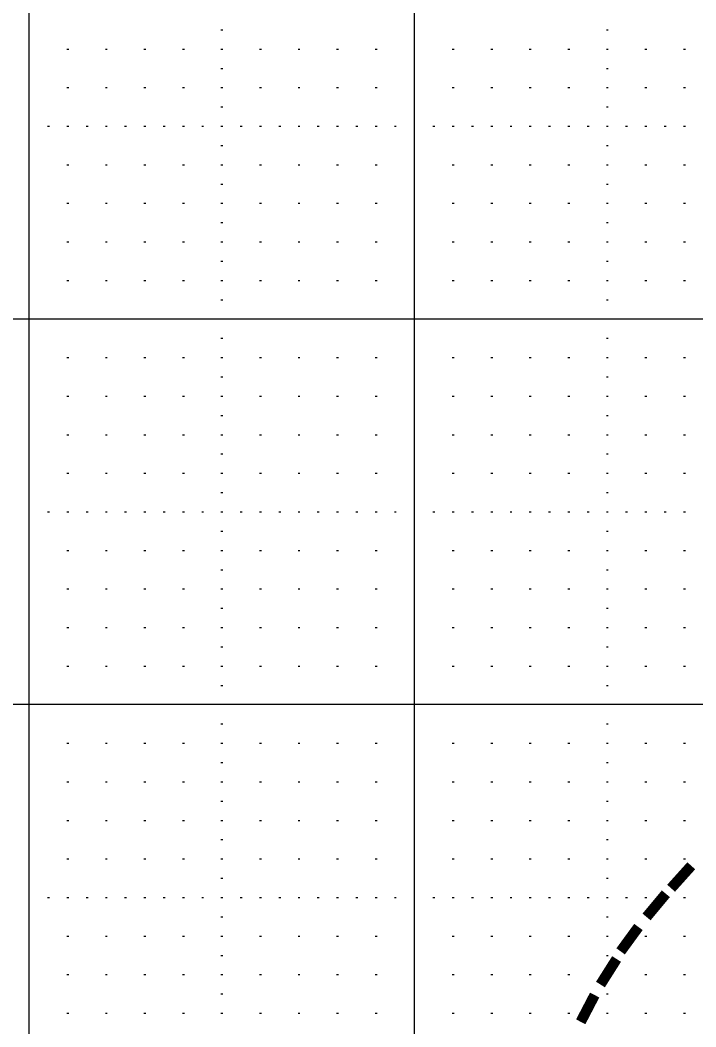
# Model space of a CAD drawing. Extents: x -1.3 to 32.1, y -0.2 to 20.7.
# Drawn here: x 20.721 to 22.475, y 2.458 to 5.068 of the extents above; entities that cross this region are included whole.
import ezdxf

# ---------------------------------------------------------------- set-up
doc = ezdxf.new("R2010")
doc.units = 0
for name, color, linetype in [('Level 49', 7, 'Continuous'), ('Level 5', 7, 'Continuous'), ('Level 6', 7, 'Continuous')]:
    doc.layers.add(name, color=color, linetype=linetype)

msp = doc.modelspace()

# ---------------------------------------------------------------- linework, layer by layer
at = {"layer": 'Level 5'}
for p, q in [((21.2425, 5.043), (21.2475, 5.043)), ((22.2425, 5.043), (22.2475, 5.043)), ((20.8425, 4.993), (20.8475, 4.993)), ((20.9425, 4.993), (20.9475, 4.993)), ((21.0425, 4.993), (21.0475, 4.993)), ((21.1425, 4.993), (21.1475, 4.993)), ((21.2425, 4.993), (21.2475, 4.993)), ((21.3425, 4.993), (21.3475, 4.993)), ((21.4425, 4.993), (21.4475, 4.993)), ((21.5425, 4.993), (21.5475, 4.993)), ((21.6425, 4.993), (21.6475, 4.993)), ((21.8425, 4.993), (21.8475, 4.993)), ((21.9425, 4.993), (21.9475, 4.993)), ((22.0425, 4.993), (22.0475, 4.993)), ((22.1425, 4.993), (22.1475, 4.993)), ((22.2425, 4.993), (22.2475, 4.993)), ((22.3425, 4.993), (22.3475, 4.993)), ((22.4425, 4.993), (22.4475, 4.993)), ((21.2425, 4.943), (21.2475, 4.943)), ((22.2425, 4.943), (22.2475, 4.943)), ((20.8425, 4.893), (20.8475, 4.893)), ((20.9425, 4.893), (20.9475, 4.893)), ((21.0425, 4.893), (21.0475, 4.893)), ((21.1425, 4.893), (21.1475, 4.893)), ((21.2425, 4.893), (21.2475, 4.893)), ((21.3425, 4.893), (21.3475, 4.893)), ((21.4425, 4.893), (21.4475, 4.893)), ((21.5425, 4.893), (21.5475, 4.893)), ((21.6425, 4.893), (21.6475, 4.893)), ((21.8425, 4.893), (21.8475, 4.893)), ((21.9425, 4.893), (21.9475, 4.893)), ((22.0425, 4.893), (22.0475, 4.893)), ((22.1425, 4.893), (22.1475, 4.893)), ((22.2425, 4.893), (22.2475, 4.893)), ((22.3425, 4.893), (22.3475, 4.893)), ((22.4425, 4.893), (22.4475, 4.893)), ((21.2425, 4.843), (21.2475, 4.843)), ((22.2425, 4.843), (22.2475, 4.843)), ((20.7925, 4.793), (20.7975, 4.793)), ((20.8425, 4.793), (20.8475, 4.793)), ((20.8925, 4.793), (20.8975, 4.793)), ((20.9425, 4.793), (20.9475, 4.793)), ((20.9925, 4.793), (20.9975, 4.793)), ((21.0425, 4.793), (21.0475, 4.793)), ((21.0925, 4.793), (21.0975, 4.793)), ((21.1425, 4.793), (21.1475, 4.793)), ((21.1925, 4.793), (21.1975, 4.793)), ((21.2425, 4.793), (21.2475, 4.793)), ((21.2925, 4.793), (21.2975, 4.793)), ((21.3425, 4.793), (21.3475, 4.793)), ((21.3925, 4.793), (21.3975, 4.793)), ((21.4425, 4.793), (21.4475, 4.793)), ((21.4925, 4.793), (21.4975, 4.793)), ((21.5425, 4.793), (21.5475, 4.793)), ((21.5925, 4.793), (21.5975, 4.793)), ((21.6425, 4.793), (21.6475, 4.793)), ((21.6925, 4.793), (21.6975, 4.793)), ((21.7925, 4.793), (21.7975, 4.793)), ((21.8425, 4.793), (21.8475, 4.793)), ((21.8925, 4.793), (21.8975, 4.793)), ((21.9425, 4.793), (21.9475, 4.793)), ((21.9925, 4.793), (21.9975, 4.793)), ((22.0425, 4.793), (22.0475, 4.793)), ((22.0925, 4.793), (22.0975, 4.793)), ((22.1425, 4.793), (22.1475, 4.793)), ((22.1925, 4.793), (22.1975, 4.793)), ((22.2425, 4.793), (22.2475, 4.793)), ((22.2925, 4.793), (22.2975, 4.793)), ((22.3425, 4.793), (22.3475, 4.793)), ((22.3925, 4.793), (22.3975, 4.793)), ((22.4425, 4.793), (22.4475, 4.793)), ((21.2425, 4.743), (21.2475, 4.743)), ((22.2425, 4.743), (22.2475, 4.743)), ((20.8425, 4.693), (20.8475, 4.693)), ((20.9425, 4.693), (20.9475, 4.693)), ((21.0425, 4.693), (21.0475, 4.693)), ((21.1425, 4.693), (21.1475, 4.693)), ((21.2425, 4.693), (21.2475, 4.693)), ((21.3425, 4.693), (21.3475, 4.693)), ((21.4425, 4.693), (21.4475, 4.693)), ((21.5425, 4.693), (21.5475, 4.693)), ((21.6425, 4.693), (21.6475, 4.693)), ((21.8425, 4.693), (21.8475, 4.693)), ((21.9425, 4.693), (21.9475, 4.693)), ((22.0425, 4.693), (22.0475, 4.693)), ((22.1425, 4.693), (22.1475, 4.693)), ((22.2425, 4.693), (22.2475, 4.693)), ((22.3425, 4.693), (22.3475, 4.693)), ((22.4425, 4.693), (22.4475, 4.693)), ((21.2425, 4.643), (21.2475, 4.643)), ((22.2425, 4.643), (22.2475, 4.643)), ((20.8425, 4.593), (20.8475, 4.593)), ((20.9425, 4.593), (20.9475, 4.593)), ((21.0425, 4.593), (21.0475, 4.593)), ((21.1425, 4.593), (21.1475, 4.593)), ((21.2425, 4.593), (21.2475, 4.593)), ((21.3425, 4.593), (21.3475, 4.593)), ((21.4425, 4.593), (21.4475, 4.593)), ((21.5425, 4.593), (21.5475, 4.593)), ((21.6425, 4.593), (21.6475, 4.593)), ((21.8425, 4.593), (21.8475, 4.593)), ((21.9425, 4.593), (21.9475, 4.593)), ((22.0425, 4.593), (22.0475, 4.593)), ((22.1425, 4.593), (22.1475, 4.593)), ((22.2425, 4.593), (22.2475, 4.593)), ((22.3425, 4.593), (22.3475, 4.593)), ((22.4425, 4.593), (22.4475, 4.593)), ((21.2425, 4.543), (21.2475, 4.543)), ((22.2425, 4.543), (22.2475, 4.543)), ((20.8425, 4.493), (20.8475, 4.493)), ((20.9425, 4.493), (20.9475, 4.493)), ((21.0425, 4.493), (21.0475, 4.493)), ((21.1425, 4.493), (21.1475, 4.493)), ((21.2425, 4.493), (21.2475, 4.493)), ((21.3425, 4.493), (21.3475, 4.493)), ((21.4425, 4.493), (21.4475, 4.493)), ((21.5425, 4.493), (21.5475, 4.493)), ((21.6425, 4.493), (21.6475, 4.493)), ((21.8425, 4.493), (21.8475, 4.493)), ((21.9425, 4.493), (21.9475, 4.493)), ((22.0425, 4.493), (22.0475, 4.493)), ((22.1425, 4.493), (22.1475, 4.493)), ((22.2425, 4.493), (22.2475, 4.493)), ((22.3425, 4.493), (22.3475, 4.493)), ((22.4425, 4.493), (22.4475, 4.493)), ((21.2425, 4.443), (21.2475, 4.443)), ((22.2425, 4.443), (22.2475, 4.443)), ((20.8425, 4.393), (20.8475, 4.393)), ((20.9425, 4.393), (20.9475, 4.393)), ((21.0425, 4.393), (21.0475, 4.393)), ((21.1425, 4.393), (21.1475, 4.393)), ((21.2425, 4.393), (21.2475, 4.393)), ((21.3425, 4.393), (21.3475, 4.393)), ((21.4425, 4.393), (21.4475, 4.393)), ((21.5425, 4.393), (21.5475, 4.393)), ((21.6425, 4.393), (21.6475, 4.393)), ((21.8425, 4.393), (21.8475, 4.393)), ((21.9425, 4.393), (21.9475, 4.393)), ((22.0425, 4.393), (22.0475, 4.393)), ((22.1425, 4.393), (22.1475, 4.393)), ((22.2425, 4.393), (22.2475, 4.393)), ((22.3425, 4.393), (22.3475, 4.393)), ((22.4425, 4.393), (22.4475, 4.393)), ((21.2425, 4.343), (21.2475, 4.343)), ((22.2425, 4.343), (22.2475, 4.343)), ((21.2425, 4.243), (21.2475, 4.243)), ((22.2425, 4.243), (22.2475, 4.243)), ((20.8425, 4.193), (20.8475, 4.193)), ((20.9425, 4.193), (20.9475, 4.193)), ((21.0425, 4.193), (21.0475, 4.193)), ((21.1425, 4.193), (21.1475, 4.193)), ((21.2425, 4.193), (21.2475, 4.193)), ((21.3425, 4.193), (21.3475, 4.193)), ((21.4425, 4.193), (21.4475, 4.193)), ((21.5425, 4.193), (21.5475, 4.193)), ((21.6425, 4.193), (21.6475, 4.193)), ((21.8425, 4.193), (21.8475, 4.193)), ((21.9425, 4.193), (21.9475, 4.193)), ((22.0425, 4.193), (22.0475, 4.193)), ((22.1425, 4.193), (22.1475, 4.193)), ((22.2425, 4.193), (22.2475, 4.193)), ((22.3425, 4.193), (22.3475, 4.193)), ((22.4425, 4.193), (22.4475, 4.193)), ((21.2425, 4.143), (21.2475, 4.143)), ((22.2425, 4.143), (22.2475, 4.143)), ((20.8425, 4.093), (20.8475, 4.093)), ((20.9425, 4.093), (20.9475, 4.093)), ((21.0425, 4.093), (21.0475, 4.093)), ((21.1425, 4.093), (21.1475, 4.093)), ((21.2425, 4.093), (21.2475, 4.093)), ((21.3425, 4.093), (21.3475, 4.093)), ((21.4425, 4.093), (21.4475, 4.093)), ((21.5425, 4.093), (21.5475, 4.093)), ((21.6425, 4.093), (21.6475, 4.093)), ((21.8425, 4.093), (21.8475, 4.093)), ((21.9425, 4.093), (21.9475, 4.093)), ((22.0425, 4.093), (22.0475, 4.093)), ((22.1425, 4.093), (22.1475, 4.093)), ((22.2425, 4.093), (22.2475, 4.093)), ((22.3425, 4.093), (22.3475, 4.093)), ((22.4425, 4.093), (22.4475, 4.093)), ((21.2425, 4.043), (21.2475, 4.043)), ((22.2425, 4.043), (22.2475, 4.043)), ((20.8425, 3.993), (20.8475, 3.993)), ((20.9425, 3.993), (20.9475, 3.993)), ((21.0425, 3.993), (21.0475, 3.993)), ((21.1425, 3.993), (21.1475, 3.993)), ((21.2425, 3.993), (21.2475, 3.993)), ((21.3425, 3.993), (21.3475, 3.993)), ((21.4425, 3.993), (21.4475, 3.993)), ((21.5425, 3.993), (21.5475, 3.993)), ((21.6425, 3.993), (21.6475, 3.993)), ((21.8425, 3.993), (21.8475, 3.993)), ((21.9425, 3.993), (21.9475, 3.993)), ((22.0425, 3.993), (22.0475, 3.993)), ((22.1425, 3.993), (22.1475, 3.993)), ((22.2425, 3.993), (22.2475, 3.993)), ((22.3425, 3.993), (22.3475, 3.993)), ((22.4425, 3.993), (22.4475, 3.993)), ((21.2425, 3.943), (21.2475, 3.943)), ((22.2425, 3.943), (22.2475, 3.943)), ((20.8425, 3.893), (20.8475, 3.893)), ((20.9425, 3.893), (20.9475, 3.893)), ((21.0425, 3.893), (21.0475, 3.893)), ((21.1425, 3.893), (21.1475, 3.893)), ((21.2425, 3.893), (21.2475, 3.893)), ((21.3425, 3.893), (21.3475, 3.893)), ((21.4425, 3.893), (21.4475, 3.893)), ((21.5425, 3.893), (21.5475, 3.893)), ((21.6425, 3.893), (21.6475, 3.893)), ((21.8425, 3.893), (21.8475, 3.893)), ((21.9425, 3.893), (21.9475, 3.893)), ((22.0425, 3.893), (22.0475, 3.893)), ((22.1425, 3.893), (22.1475, 3.893)), ((22.2425, 3.893), (22.2475, 3.893)), ((22.3425, 3.893), (22.3475, 3.893)), ((22.4425, 3.893), (22.4475, 3.893)), ((21.2425, 3.843), (21.2475, 3.843)), ((22.2425, 3.843), (22.2475, 3.843)), ((20.7925, 3.793), (20.7975, 3.793)), ((20.8425, 3.793), (20.8475, 3.793)), ((20.8925, 3.793), (20.8975, 3.793)), ((20.9425, 3.793), (20.9475, 3.793)), ((20.9925, 3.793), (20.9975, 3.793)), ((21.0425, 3.793), (21.0475, 3.793)), ((21.0925, 3.793), (21.0975, 3.793)), ((21.1425, 3.793), (21.1475, 3.793)), ((21.1925, 3.793), (21.1975, 3.793)), ((21.2425, 3.793), (21.2475, 3.793)), ((21.2925, 3.793), (21.2975, 3.793)), ((21.3425, 3.793), (21.3475, 3.793)), ((21.3925, 3.793), (21.3975, 3.793)), ((21.4425, 3.793), (21.4475, 3.793)), ((21.4925, 3.793), (21.4975, 3.793)), ((21.5425, 3.793), (21.5475, 3.793)), ((21.5925, 3.793), (21.5975, 3.793)), ((21.6425, 3.793), (21.6475, 3.793)), ((21.6925, 3.793), (21.6975, 3.793)), ((21.7925, 3.793), (21.7975, 3.793)), ((21.8425, 3.793), (21.8475, 3.793)), ((21.8925, 3.793), (21.8975, 3.793)), ((21.9425, 3.793), (21.9475, 3.793)), ((21.9925, 3.793), (21.9975, 3.793)), ((22.0425, 3.793), (22.0475, 3.793)), ((22.0925, 3.793), (22.0975, 3.793)), ((22.1425, 3.793), (22.1475, 3.793)), ((22.1925, 3.793), (22.1975, 3.793)), ((22.2425, 3.793), (22.2475, 3.793)), ((22.2925, 3.793), (22.2975, 3.793)), ((22.3425, 3.793), (22.3475, 3.793)), ((22.3925, 3.793), (22.3975, 3.793)), ((22.4425, 3.793), (22.4475, 3.793)), ((21.2425, 3.743), (21.2475, 3.743)), ((22.2425, 3.743), (22.2475, 3.743)), ((20.8425, 3.693), (20.8475, 3.693)), ((20.9425, 3.693), (20.9475, 3.693)), ((21.0425, 3.693), (21.0475, 3.693)), ((21.1425, 3.693), (21.1475, 3.693)), ((21.2425, 3.693), (21.2475, 3.693)), ((21.3425, 3.693), (21.3475, 3.693)), ((21.4425, 3.693), (21.4475, 3.693)), ((21.5425, 3.693), (21.5475, 3.693)), ((21.6425, 3.693), (21.6475, 3.693)), ((21.8425, 3.693), (21.8475, 3.693)), ((21.9425, 3.693), (21.9475, 3.693)), ((22.0425, 3.693), (22.0475, 3.693)), ((22.1425, 3.693), (22.1475, 3.693)), ((22.2425, 3.693), (22.2475, 3.693)), ((22.3425, 3.693), (22.3475, 3.693)), ((22.4425, 3.693), (22.4475, 3.693)), ((21.2425, 3.643), (21.2475, 3.643)), ((22.2425, 3.643), (22.2475, 3.643)), ((20.8425, 3.593), (20.8475, 3.593)), ((20.9425, 3.593), (20.9475, 3.593)), ((21.0425, 3.593), (21.0475, 3.593)), ((21.1425, 3.593), (21.1475, 3.593)), ((21.2425, 3.593), (21.2475, 3.593)), ((21.3425, 3.593), (21.3475, 3.593)), ((21.4425, 3.593), (21.4475, 3.593)), ((21.5425, 3.593), (21.5475, 3.593)), ((21.6425, 3.593), (21.6475, 3.593)), ((21.8425, 3.593), (21.8475, 3.593)), ((21.9425, 3.593), (21.9475, 3.593)), ((22.0425, 3.593), (22.0475, 3.593)), ((22.1425, 3.593), (22.1475, 3.593)), ((22.2425, 3.593), (22.2475, 3.593)), ((22.3425, 3.593), (22.3475, 3.593)), ((22.4425, 3.593), (22.4475, 3.593)), ((21.2425, 3.543), (21.2475, 3.543)), ((22.2425, 3.543), (22.2475, 3.543)), ((20.8425, 3.493), (20.8475, 3.493)), ((20.9425, 3.493), (20.9475, 3.493)), ((21.0425, 3.493), (21.0475, 3.493)), ((21.1425, 3.493), (21.1475, 3.493)), ((21.2425, 3.493), (21.2475, 3.493)), ((21.3425, 3.493), (21.3475, 3.493)), ((21.4425, 3.493), (21.4475, 3.493)), ((21.5425, 3.493), (21.5475, 3.493)), ((21.6425, 3.493), (21.6475, 3.493)), ((21.8425, 3.493), (21.8475, 3.493)), ((21.9425, 3.493), (21.9475, 3.493)), ((22.0425, 3.493), (22.0475, 3.493)), ((22.1425, 3.493), (22.1475, 3.493)), ((22.2425, 3.493), (22.2475, 3.493)), ((22.3425, 3.493), (22.3475, 3.493)), ((22.4425, 3.493), (22.4475, 3.493)), ((21.2425, 3.443), (21.2475, 3.443)), ((22.2425, 3.443), (22.2475, 3.443)), ((20.8425, 3.393), (20.8475, 3.393)), ((20.9425, 3.393), (20.9475, 3.393)), ((21.0425, 3.393), (21.0475, 3.393)), ((21.1425, 3.393), (21.1475, 3.393)), ((21.2425, 3.393), (21.2475, 3.393)), ((21.3425, 3.393), (21.3475, 3.393)), ((21.4425, 3.393), (21.4475, 3.393)), ((21.5425, 3.393), (21.5475, 3.393)), ((21.6425, 3.393), (21.6475, 3.393)), ((21.8425, 3.393), (21.8475, 3.393)), ((21.9425, 3.393), (21.9475, 3.393)), ((22.0425, 3.393), (22.0475, 3.393)), ((22.1425, 3.393), (22.1475, 3.393)), ((22.2425, 3.393), (22.2475, 3.393)), ((22.3425, 3.393), (22.3475, 3.393)), ((22.4425, 3.393), (22.4475, 3.393)), ((21.2425, 3.343), (21.2475, 3.343)), ((22.2425, 3.343), (22.2475, 3.343)), ((21.2425, 3.243), (21.2475, 3.243)), ((22.2425, 3.243), (22.2475, 3.243)), ((20.8425, 3.193), (20.8475, 3.193)), ((20.9425, 3.193), (20.9475, 3.193)), ((21.0425, 3.193), (21.0475, 3.193)), ((21.1425, 3.193), (21.1475, 3.193)), ((21.2425, 3.193), (21.2475, 3.193)), ((21.3425, 3.193), (21.3475, 3.193)), ((21.4425, 3.193), (21.4475, 3.193)), ((21.5425, 3.193), (21.5475, 3.193)), ((21.6425, 3.193), (21.6475, 3.193)), ((21.8425, 3.193), (21.8475, 3.193)), ((21.9425, 3.193), (21.9475, 3.193)), ((22.0425, 3.193), (22.0475, 3.193)), ((22.1425, 3.193), (22.1475, 3.193)), ((22.2425, 3.193), (22.2475, 3.193)), ((22.3425, 3.193), (22.3475, 3.193)), ((22.4425, 3.193), (22.4475, 3.193)), ((21.2425, 3.143), (21.2475, 3.143)), ((22.2425, 3.143), (22.2475, 3.143)), ((20.8425, 3.093), (20.8475, 3.093)), ((20.9425, 3.093), (20.9475, 3.093)), ((21.0425, 3.093), (21.0475, 3.093)), ((21.1425, 3.093), (21.1475, 3.093)), ((21.2425, 3.093), (21.2475, 3.093)), ((21.3425, 3.093), (21.3475, 3.093)), ((21.4425, 3.093), (21.4475, 3.093)), ((21.5425, 3.093), (21.5475, 3.093)), ((21.6425, 3.093), (21.6475, 3.093)), ((21.8425, 3.093), (21.8475, 3.093)), ((21.9425, 3.093), (21.9475, 3.093)), ((22.0425, 3.093), (22.0475, 3.093)), ((22.1425, 3.093), (22.1475, 3.093)), ((22.2425, 3.093), (22.2475, 3.093)), ((22.3425, 3.093), (22.3475, 3.093)), ((22.4425, 3.093), (22.4475, 3.093)), ((21.2425, 3.043), (21.2475, 3.043)), ((22.2425, 3.043), (22.2475, 3.043)), ((20.8425, 2.993), (20.8475, 2.993)), ((20.9425, 2.993), (20.9475, 2.993)), ((21.0425, 2.993), (21.0475, 2.993)), ((21.1425, 2.993), (21.1475, 2.993)), ((21.2425, 2.993), (21.2475, 2.993)), ((21.3425, 2.993), (21.3475, 2.993)), ((21.4425, 2.993), (21.4475, 2.993)), ((21.5425, 2.993), (21.5475, 2.993)), ((21.6425, 2.993), (21.6475, 2.993)), ((21.8425, 2.993), (21.8475, 2.993)), ((21.9425, 2.993), (21.9475, 2.993)), ((22.0425, 2.993), (22.0475, 2.993)), ((22.1425, 2.993), (22.1475, 2.993)), ((22.2425, 2.993), (22.2475, 2.993)), ((22.3425, 2.993), (22.3475, 2.993)), ((22.4425, 2.993), (22.4475, 2.993)), ((21.2425, 2.943), (21.2475, 2.943)), ((22.2425, 2.943), (22.2475, 2.943)), ((20.8425, 2.893), (20.8475, 2.893)), ((20.9425, 2.893), (20.9475, 2.893)), ((21.0425, 2.893), (21.0475, 2.893)), ((21.1425, 2.893), (21.1475, 2.893)), ((21.2425, 2.893), (21.2475, 2.893)), ((21.3425, 2.893), (21.3475, 2.893)), ((21.4425, 2.893), (21.4475, 2.893)), ((21.5425, 2.893), (21.5475, 2.893)), ((21.6425, 2.893), (21.6475, 2.893)), ((21.8425, 2.893), (21.8475, 2.893)), ((21.9425, 2.893), (21.9475, 2.893)), ((22.0425, 2.893), (22.0475, 2.893)), ((22.1425, 2.893), (22.1475, 2.893)), ((22.2425, 2.893), (22.2475, 2.893)), ((22.3425, 2.893), (22.3475, 2.893)), ((22.4425, 2.893), (22.4475, 2.893)), ((21.2425, 2.843), (21.2475, 2.843)), ((22.2425, 2.843), (22.2475, 2.843)), ((20.7925, 2.793), (20.7975, 2.793)), ((20.8425, 2.793), (20.8475, 2.793)), ((20.8925, 2.793), (20.8975, 2.793)), ((20.9425, 2.793), (20.9475, 2.793)), ((20.9925, 2.793), (20.9975, 2.793)), ((21.0425, 2.793), (21.0475, 2.793)), ((21.0925, 2.793), (21.0975, 2.793)), ((21.1425, 2.793), (21.1475, 2.793)), ((21.1925, 2.793), (21.1975, 2.793)), ((21.2425, 2.793), (21.2475, 2.793)), ((21.2925, 2.793), (21.2975, 2.793)), ((21.3425, 2.793), (21.3475, 2.793)), ((21.3925, 2.793), (21.3975, 2.793)), ((21.4425, 2.793), (21.4475, 2.793)), ((21.4925, 2.793), (21.4975, 2.793)), ((21.5425, 2.793), (21.5475, 2.793)), ((21.5925, 2.793), (21.5975, 2.793)), ((21.6425, 2.793), (21.6475, 2.793)), ((21.6925, 2.793), (21.6975, 2.793)), ((21.7925, 2.793), (21.7975, 2.793)), ((21.8425, 2.793), (21.8475, 2.793)), ((21.8925, 2.793), (21.8975, 2.793)), ((21.9425, 2.793), (21.9475, 2.793)), ((21.9925, 2.793), (21.9975, 2.793)), ((22.0425, 2.793), (22.0475, 2.793)), ((22.0925, 2.793), (22.0975, 2.793)), ((22.1425, 2.793), (22.1475, 2.793)), ((22.1925, 2.793), (22.1975, 2.793)), ((22.2425, 2.793), (22.2475, 2.793)), ((22.2925, 2.793), (22.2975, 2.793)), ((22.3425, 2.793), (22.3475, 2.793)), ((22.3925, 2.793), (22.3975, 2.793)), ((22.4425, 2.793), (22.4475, 2.793)), ((21.2425, 2.743), (21.2475, 2.743)), ((22.2425, 2.743), (22.2475, 2.743)), ((20.8425, 2.693), (20.8475, 2.693)), ((20.9425, 2.693), (20.9475, 2.693)), ((21.0425, 2.693), (21.0475, 2.693)), ((21.1425, 2.693), (21.1475, 2.693)), ((21.2425, 2.693), (21.2475, 2.693)), ((21.3425, 2.693), (21.3475, 2.693)), ((21.4425, 2.693), (21.4475, 2.693)), ((21.5425, 2.693), (21.5475, 2.693)), ((21.6425, 2.693), (21.6475, 2.693)), ((21.8425, 2.693), (21.8475, 2.693)), ((21.9425, 2.693), (21.9475, 2.693)), ((22.0425, 2.693), (22.0475, 2.693)), ((22.1425, 2.693), (22.1475, 2.693)), ((22.2425, 2.693), (22.2475, 2.693)), ((22.3425, 2.693), (22.3475, 2.693)), ((22.4425, 2.693), (22.4475, 2.693)), ((21.2425, 2.643), (21.2475, 2.643)), ((22.2425, 2.643), (22.2475, 2.643)), ((20.8425, 2.593), (20.8475, 2.593)), ((20.9425, 2.593), (20.9475, 2.593)), ((21.0425, 2.593), (21.0475, 2.593)), ((21.1425, 2.593), (21.1475, 2.593)), ((21.2425, 2.593), (21.2475, 2.593)), ((21.3425, 2.593), (21.3475, 2.593)), ((21.4425, 2.593), (21.4475, 2.593)), ((21.5425, 2.593), (21.5475, 2.593)), ((21.6425, 2.593), (21.6475, 2.593)), ((21.8425, 2.593), (21.8475, 2.593)), ((21.9425, 2.593), (21.9475, 2.593)), ((22.0425, 2.593), (22.0475, 2.593)), ((22.1425, 2.593), (22.1475, 2.593)), ((22.2425, 2.593), (22.2475, 2.593)), ((22.3425, 2.593), (22.3475, 2.593)), ((22.4425, 2.593), (22.4475, 2.593)), ((21.2425, 2.543), (21.2475, 2.543)), ((22.2425, 2.543), (22.2475, 2.543)), ((20.8425, 2.493), (20.8475, 2.493)), ((20.9425, 2.493), (20.9475, 2.493)), ((21.0425, 2.493), (21.0475, 2.493)), ((21.1425, 2.493), (21.1475, 2.493)), ((21.2425, 2.493), (21.2475, 2.493)), ((21.3425, 2.493), (21.3475, 2.493)), ((21.4425, 2.493), (21.4475, 2.493)), ((21.5425, 2.493), (21.5475, 2.493)), ((21.6425, 2.493), (21.6475, 2.493)), ((21.8425, 2.493), (21.8475, 2.493)), ((21.9425, 2.493), (21.9475, 2.493)), ((22.0425, 2.493), (22.0475, 2.493)), ((22.1425, 2.493), (22.1475, 2.493)), ((22.2425, 2.493), (22.2475, 2.493)), ((22.3425, 2.493), (22.3475, 2.493)), ((22.4425, 2.493), (22.4475, 2.493))]:
    msp.add_line(p, q, dxfattribs=at)
at = {"layer": 'Level 6'}
for p, q in [((20.745, 0.293), (20.745, 10.293)), ((21.745, 0.293), (21.745, 10.293)), ((31.617, 4.293), (-0.001, 4.293)), ((31.617, 3.293), (-0.001, 3.293))]:
    msp.add_line(p, q, dxfattribs=at)

# ---------------------------------------------------------------- texts
at = {"layer": 'Level 49'}
for rotation, p in [(48.0254, (22.4698, 2.7445)), (50.2166, (22.4088, 2.6723)), (53.8349, (22.3459, 2.5872)), (57.673, (22.2978, 2.5058)), (62.4738, (22.2515, 2.4152))]:
    msp.add_text('-', height=0.2398, rotation=rotation, dxfattribs=at).set_placement(p)

doc.saveas('drawing.dxf')
